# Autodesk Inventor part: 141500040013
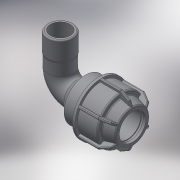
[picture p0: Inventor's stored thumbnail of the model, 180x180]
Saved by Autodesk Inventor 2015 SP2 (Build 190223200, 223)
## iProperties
Created: 2017-08
Part Number: 141500040013
Material: Generic
Description: L.14 90° ELBOW FEMALE ADAPTOR (SILVER) 40-1.1/4"
Document SubType Name: Modeling
Designer: KIM
Density: 1 g/cm^3
Appearance: Default
Author: KIM
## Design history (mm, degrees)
derived "141500.ipt"
feature "Solid1::141500.ipt"
feature "Solid2::141500.ipt"
tag "TaggingFeature1"
body "Solid1"
body "Solid2"
other parameters: "d2" = 62, "d4" = 15 deg, "d5" = 40.92, "d6" = 13.5036, "d10" = 73, "d16" = 40.8, "d17" = 3.1, "d22" = 64, "d24" = 3.1, "d25" = 65.7, "d26" = 54.75, "d27" = 3.1, "d28" = 135 deg, "d29" = 1.86, "d31" = 2, "d46" = 150 deg, "d49" = 3.65, "d50" = 0, "d58" = 1.2, "d61" = 360 deg, "d63" = 36, "d95" = 38.952, "d96" = 50.6376, "d97" = 25, "d98" = 31.1616, "d99" = 45.57384, "d100" = 135 deg, "d108" = 2, "d112" = 32.5, "d113" = 86, "d114" = 63.24, "d115" = 45.57384, "d116" = 45 deg, "d117" = 0, "d118" = 0, "G_" = 38.952, "E_" = 73, "A_" = 86, "l_" = 62, "l_2" = 25
